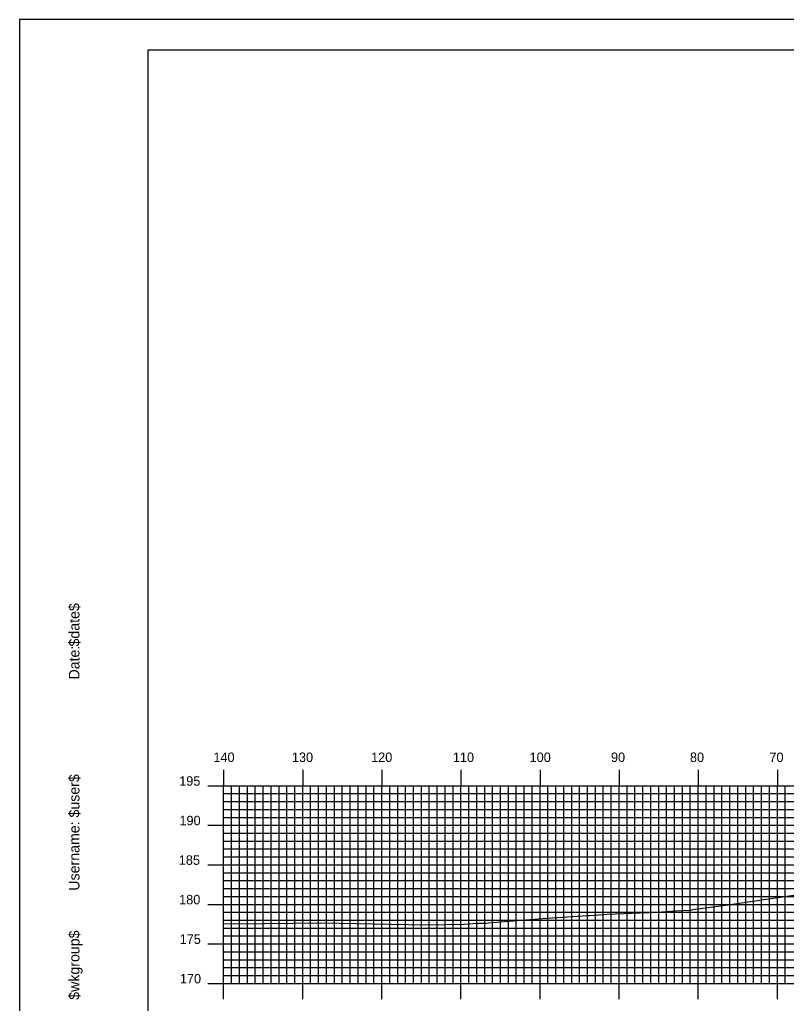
# Model space of a CAD drawing. Extents: x 1823573 to 1823916, y 442591 to 442811.
# Drawn here: x 1823572.5 to 1823669.4, y 442686.2 to 442810.5 of the extents above; entities that cross this region are included whole.
import ezdxf

# ---------------------------------------------------------------- set-up
doc = ezdxf.new("R2010")
doc.units = 0
for name, color, linetype in [('BORDER', 7, 'Continuous'), ('H_V ANNOTATION', 7, 'Continuous'), ('MAJOR', 7, 'Continuous'), ('MINOR', 7, 'Continuous'), ('PLOT BOUNDARY', 7, 'Continuous'), ('S_Roadway_Centerline', 7, 'Continuous')]:
    doc.layers.add(name, color=color, linetype=linetype)

msp = doc.modelspace()

# ---------------------------------------------------------------- linework, layer by layer
at = {"layer": 'BORDER'}
msp.add_lwpolyline([(1823588.71, 442596.67), (1823908.71, 442596.67), (1823908.71, 442806.67), (1823588.71, 442806.67)], close=True, dxfattribs=at)
at = {"layer": 'MAJOR'}
for p, q in [((1823598.31, 442715.67), (1823598.31, 442713.67)), ((1823608.31, 442715.67), (1823608.31, 442713.67)), ((1823618.31, 442715.67), (1823618.31, 442713.67)), ((1823628.31, 442715.67), (1823628.31, 442713.67)), ((1823638.31, 442715.67), (1823638.31, 442713.67)), ((1823648.31, 442715.67), (1823648.31, 442713.67)), ((1823658.31, 442715.67), (1823658.31, 442713.67)), ((1823668.31, 442715.67), (1823668.31, 442713.67)), ((1823596.3, 442713.67), (1823598.31, 442713.67)), ((1823598.31, 442713.67), (1823878.31, 442713.67)), ((1823598.31, 442688.67), (1823598.31, 442713.67)), ((1823598.31, 442688.67), (1823598.31, 442713.67)), ((1823598.31, 442713.67), (1823878.31, 442713.67)), ((1823608.31, 442688.67), (1823608.31, 442713.67)), ((1823618.31, 442688.67), (1823618.31, 442713.67)), ((1823628.31, 442688.67), (1823628.31, 442713.67)), ((1823638.31, 442688.67), (1823638.31, 442713.67)), ((1823648.31, 442688.67), (1823648.31, 442713.67)), ((1823658.31, 442688.67), (1823658.31, 442713.67)), ((1823668.31, 442688.67), (1823668.31, 442713.67)), ((1823596.3, 442708.67), (1823598.31, 442708.67)), ((1823598.31, 442708.67), (1823878.31, 442708.67)), ((1823596.3, 442703.67), (1823598.31, 442703.67)), ((1823598.31, 442703.67), (1823878.31, 442703.67)), ((1823596.3, 442698.67), (1823598.31, 442698.67)), ((1823598.31, 442698.67), (1823878.31, 442698.67)), ((1823596.3, 442693.67), (1823598.31, 442693.67)), ((1823598.31, 442693.67), (1823878.31, 442693.67)), ((1823596.3, 442688.67), (1823598.31, 442688.67)), ((1823598.31, 442688.67), (1823878.31, 442688.67)), ((1823598.31, 442688.67), (1823878.31, 442688.67)), ((1823598.31, 442686.66), (1823598.31, 442688.67)), ((1823608.31, 442686.66), (1823608.31, 442688.67)), ((1823618.31, 442686.66), (1823618.31, 442688.67)), ((1823628.31, 442686.66), (1823628.31, 442688.67)), ((1823638.31, 442686.66), (1823638.31, 442688.67)), ((1823648.31, 442686.66), (1823648.31, 442688.67)), ((1823658.31, 442686.66), (1823658.31, 442688.67)), ((1823668.31, 442686.66), (1823668.31, 442688.67))]:
    msp.add_line(p, q, dxfattribs=at)
at = {"layer": 'MINOR'}
for p, q in [((1823599.31, 442688.67), (1823599.31, 442713.67)), ((1823600.31, 442688.67), (1823600.31, 442713.67)), ((1823601.31, 442688.67), (1823601.31, 442713.67)), ((1823602.31, 442688.67), (1823602.31, 442713.67)), ((1823603.31, 442688.67), (1823603.31, 442713.67)), ((1823604.31, 442688.67), (1823604.31, 442713.67)), ((1823605.31, 442688.67), (1823605.31, 442713.67)), ((1823606.31, 442688.67), (1823606.31, 442713.67)), ((1823607.31, 442688.67), (1823607.31, 442713.67)), ((1823609.31, 442688.67), (1823609.31, 442713.67)), ((1823610.31, 442688.67), (1823610.31, 442713.67)), ((1823611.31, 442688.67), (1823611.31, 442713.67)), ((1823612.31, 442688.67), (1823612.31, 442713.67)), ((1823613.31, 442688.67), (1823613.31, 442713.67)), ((1823614.31, 442688.67), (1823614.31, 442713.67)), ((1823615.31, 442688.67), (1823615.31, 442713.67)), ((1823616.31, 442688.67), (1823616.31, 442713.67)), ((1823617.31, 442688.67), (1823617.31, 442713.67)), ((1823619.31, 442688.67), (1823619.31, 442713.67)), ((1823620.31, 442688.67), (1823620.31, 442713.67)), ((1823621.31, 442688.67), (1823621.31, 442713.67)), ((1823622.31, 442688.67), (1823622.31, 442713.67)), ((1823623.31, 442688.67), (1823623.31, 442713.67)), ((1823624.31, 442688.67), (1823624.31, 442713.67)), ((1823625.31, 442688.67), (1823625.31, 442713.67)), ((1823626.31, 442688.67), (1823626.31, 442713.67)), ((1823627.31, 442688.67), (1823627.31, 442713.67)), ((1823629.31, 442688.67), (1823629.31, 442713.67)), ((1823630.31, 442688.67), (1823630.31, 442713.67)), ((1823631.31, 442688.67), (1823631.31, 442713.67)), ((1823632.31, 442688.67), (1823632.31, 442713.67)), ((1823633.31, 442688.67), (1823633.31, 442713.67)), ((1823634.31, 442688.67), (1823634.31, 442713.67)), ((1823635.31, 442688.67), (1823635.31, 442713.67)), ((1823636.31, 442688.67), (1823636.31, 442713.67)), ((1823637.31, 442688.67), (1823637.31, 442713.67)), ((1823639.31, 442688.67), (1823639.31, 442713.67)), ((1823640.31, 442688.67), (1823640.31, 442713.67)), ((1823641.31, 442688.67), (1823641.31, 442713.67)), ((1823642.31, 442688.67), (1823642.31, 442713.67)), ((1823643.31, 442688.67), (1823643.31, 442713.67)), ((1823644.31, 442688.67), (1823644.31, 442713.67)), ((1823645.31, 442688.67), (1823645.31, 442713.67)), ((1823646.31, 442688.67), (1823646.31, 442713.67)), ((1823647.31, 442688.67), (1823647.31, 442713.67)), ((1823649.31, 442688.67), (1823649.31, 442713.67)), ((1823650.31, 442688.67), (1823650.31, 442713.67)), ((1823651.31, 442688.67), (1823651.31, 442713.67)), ((1823652.31, 442688.67), (1823652.31, 442713.67)), ((1823653.31, 442688.67), (1823653.31, 442713.67)), ((1823654.31, 442688.67), (1823654.31, 442713.67)), ((1823655.31, 442688.67), (1823655.31, 442713.67)), ((1823656.31, 442688.67), (1823656.31, 442713.67)), ((1823657.31, 442688.67), (1823657.31, 442713.67)), ((1823659.31, 442688.67), (1823659.31, 442713.67)), ((1823660.31, 442688.67), (1823660.31, 442713.67)), ((1823661.31, 442688.67), (1823661.31, 442713.67)), ((1823662.31, 442688.67), (1823662.31, 442713.67)), ((1823663.31, 442688.67), (1823663.31, 442713.67)), ((1823664.31, 442688.67), (1823664.31, 442713.67)), ((1823665.31, 442688.67), (1823665.31, 442713.67)), ((1823666.31, 442688.67), (1823666.31, 442713.67)), ((1823667.31, 442688.67), (1823667.31, 442713.67)), ((1823669.31, 442688.67), (1823669.31, 442713.67)), ((1823598.31, 442712.67), (1823878.31, 442712.67)), ((1823598.31, 442712.67), (1823600.31, 442712.67)), ((1823598.31, 442711.67), (1823878.31, 442711.67)), ((1823598.31, 442711.67), (1823600.31, 442711.67)), ((1823598.31, 442710.67), (1823878.31, 442710.67)), ((1823598.31, 442710.67), (1823600.31, 442710.67)), ((1823598.31, 442709.67), (1823878.31, 442709.67)), ((1823598.31, 442709.67), (1823600.31, 442709.67)), ((1823598.31, 442707.67), (1823878.31, 442707.67)), ((1823598.31, 442707.67), (1823600.31, 442707.67)), ((1823598.31, 442706.67), (1823878.31, 442706.67)), ((1823598.31, 442706.67), (1823600.31, 442706.67)), ((1823598.31, 442705.67), (1823878.31, 442705.67)), ((1823598.31, 442705.67), (1823600.31, 442705.67)), ((1823598.31, 442704.67), (1823878.31, 442704.67)), ((1823598.31, 442704.67), (1823600.31, 442704.67)), ((1823598.31, 442702.67), (1823878.31, 442702.67)), ((1823598.31, 442702.67), (1823600.31, 442702.67)), ((1823598.31, 442701.67), (1823878.31, 442701.67)), ((1823598.31, 442701.67), (1823600.31, 442701.67)), ((1823598.31, 442700.67), (1823878.31, 442700.67)), ((1823598.31, 442700.67), (1823600.31, 442700.67)), ((1823598.31, 442699.67), (1823878.31, 442699.67)), ((1823598.31, 442699.67), (1823600.31, 442699.67)), ((1823598.31, 442697.67), (1823878.31, 442697.67)), ((1823598.31, 442697.67), (1823600.31, 442697.67)), ((1823598.31, 442696.67), (1823878.31, 442696.67)), ((1823598.31, 442696.67), (1823600.31, 442696.67)), ((1823598.31, 442695.67), (1823878.31, 442695.67)), ((1823598.31, 442695.67), (1823600.31, 442695.67)), ((1823598.31, 442694.67), (1823878.31, 442694.67)), ((1823598.31, 442694.67), (1823600.31, 442694.67)), ((1823598.31, 442692.67), (1823878.31, 442692.67)), ((1823598.31, 442692.67), (1823600.31, 442692.67)), ((1823598.31, 442691.67), (1823878.31, 442691.67)), ((1823598.31, 442691.67), (1823600.31, 442691.67)), ((1823598.31, 442690.67), (1823878.31, 442690.67)), ((1823598.31, 442690.67), (1823600.31, 442690.67)), ((1823598.31, 442689.67), (1823878.31, 442689.67)), ((1823598.31, 442689.67), (1823600.31, 442689.67))]:
    msp.add_line(p, q, dxfattribs=at)
at = {"layer": 'PLOT BOUNDARY'}
msp.add_lwpolyline([(1823572.52, 442590.55), (1823912.52, 442590.55), (1823912.52, 442810.55), (1823572.52, 442810.55)], close=True, dxfattribs=at)
at = {"layer": 'S_Roadway_Centerline'}
msp.add_lwpolyline([(1823598.31, 442696.26), (1823599.83, 442696.21), (1823610.73, 442696.35), (1823623.86, 442696.06), (1823628.66, 442696.16), (1823630.44, 442696.29), (1823631.44, 442696.29), (1823631.76, 442696.33), (1823638.61, 442696.88), (1823644.33, 442697.27), (1823644.6, 442697.28), (1823646.78, 442697.42), (1823653.1, 442697.69), (1823655.45, 442697.84), (1823657.28, 442697.93), (1823657.62, 442698.03), (1823661.47, 442698.52), (1823670.38, 442699.84)], dxfattribs=at)

# ---------------------------------------------------------------- texts
at = {"layer": 'BORDER'}
for s, p in [('$date$', (1823580.08, 442731.28)), ('$date$', (1823580.08, 442731.28)), ('Date:', (1823580.08, 442727.1)), ('Date:', (1823580.08, 442727.1)), ('$user$', (1823580.08, 442709.65)), ('$user$', (1823580.08, 442709.65)), ('Username:', (1823580.08, 442700.4)), ('Username:', (1823580.08, 442700.4)), ('$wkgroup$', (1823580.08, 442686.6)), ('$wkgroup$', (1823580.08, 442686.6))]:
    msp.add_text(s, height=1.339, rotation=90, dxfattribs=at).set_placement(p)
at = {"layer": 'H_V ANNOTATION'}
for s, p in [('140', (1823597.01, 442716.67)), ('130', (1823606.94, 442716.67)), ('120', (1823616.95, 442716.67)), ('110', (1823627.29, 442716.67)), ('100', (1823636.99, 442716.67)), ('90', (1823647.28, 442716.67)), ('80', (1823657.26, 442716.67)), ('70', (1823667.31, 442716.67)), ('195', (1823592.69, 442713.67)), ('190', (1823592.72, 442708.67)), ('185', (1823592.64, 442703.67)), ('180', (1823592.68, 442698.67)), ('175', (1823592.75, 442693.67)), ('170', (1823592.78, 442688.67))]:
    msp.add_text(s, height=1.2, dxfattribs=at).set_placement(p)
at = {"layer": 'MAJOR'}
msp.add_text('-', height=0.012, dxfattribs=at).set_placement((1823598.3, 442688.67))

doc.saveas('drawing.dxf')
